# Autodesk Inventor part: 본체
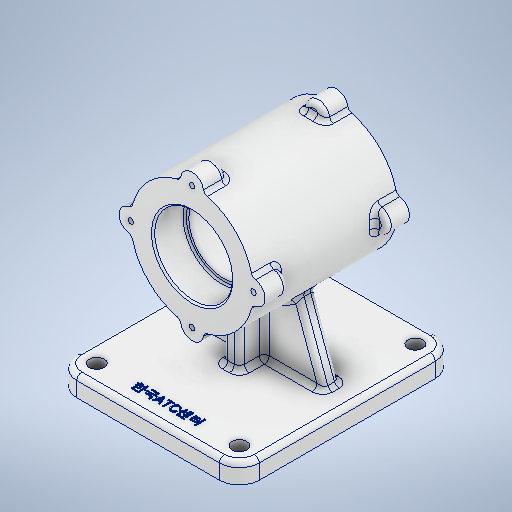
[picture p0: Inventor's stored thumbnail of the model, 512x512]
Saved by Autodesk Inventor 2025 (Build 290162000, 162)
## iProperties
Created: 2024-08
Part Number: 본체
Material: 알루미늄 6061
Document SubType Name: Modeling
Designer: SAMSUNG
Density: 2.7 g/cm^3
Appearance: 알루미늄 - 평지
Mass: 1215.33 g
Surface Area: 797.05 cm^2
Volume: 450.122 cm^3
Author: SAMSUNG
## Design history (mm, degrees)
sketch "스케치1"
  geometry: L1 (55, 70)-(-55, 70); L2 (-55, 70)-(-55, -60); L3 (-55, -60)-(55, -60); L4 (55, -60)-(55, 70); L5 (55, 70)-(-55, -60); L6 (-55, 70)-(55, -60); L7 (0, 0)-(0, 5)
  constraints: 14 end point, 2 parallel, 1 horizontal, 1 midpoint, 1 perpendicular, 1 vertical
  dimensions: "d0" = 110 distance of L2.end L3.end; "d1" = 130 distance of L1.end L2.end; "d67" = 5 distance of L7.end L7.start
extrude "돌출1" new body sketch "스케치1" distance "d2" = 12; taper "d3" = 0 deg
sketch "스케치2"
  geometry: L1 (-55, 0)-(55, 0) reference; C1 r 37 at (0, 82); 4 further points
  constraints: 3 midpoint, 1 centre point, 1 vertical alignment
  dimensions: "d5" = 37 radius of C1; "d6" = 82 distance of C1.centre point (0, 0)
extrude "돌출2" join sketch "스케치2" stored distance "d7" = 87; taper "d8" = 0 deg
sketch "스케치3"
  geometry: L1 (103, 24.5)-(82, 24.5); L2 (82, 24.5)-(82, 0); L3 (82, 0)-(103, 0); L4 (103, 0)-(103, 24.5); L5 (105.5, 43.5)-(82, 43.5); L6 (82, 43.5)-(82, 24.5); L7 (82, 24.5)-(105.5, 24.5); L8 (105.5, 24.5)-(105.5, 43.5); L9 (124.874, 0)-(25.376, 0); L10 (45, -43.5)-(119, -43.5) reference; L11 (82, -43.5)-(82, 78.341); L12 (119, 43.5)-(45, 43.5) reference; L13 (103, 0)-(103, -24.5); L14 (82, -24.5)-(82, 0); L15 (82, -24.5)-(105.5, -24.5); L16 (103, -24.5)-(82, -24.5); L17 (82, -43.5)-(82, -24.5); L18 (105.5, -43.5)-(82, -43.5); L19 (105.5, -24.5)-(105.5, -43.5); 6 further points
  constraints: 34 end point, 7 point on line, 5 symmetric about line, 4 parallel, 3 horizontal, 2 perpendicular, 1 midpoint, 1 vertical
  dimensions: "d9" = 19 distance of L7.end L5.start; "d10" = 24.5 distance of L3.end L1.start (derived); "d11" = 23.5 distance of L5.start L5.end; "d12" = 21 distance of L1.start L1.end
sketch "스케치4"
  geometry: L1 (-5, 20)-(5, 20); L2 (5, 20)-(5, -20); L3 (5, -20)-(-5, -20); L4 (-5, -20)-(-5, 20); L5 (-5, 20)-(5, -20); L6 (5, 20)-(-5, -20); L7 (-55, -70)-(55, -70) reference; 5 further points
  constraints: 12 end point, 4 midpoint, 2 parallel, 1 coincident, 1 horizontal, 1 perpendicular
  dimensions: "d20" = 10 distance of L1.start L1.end; "d22" = 40 distance of L1.end L2.end; "d69" = 50 distance between parallel lines of L7 L3
extrude "돌출3" join sketch "스케치4" stored distance "d23" = 87; taper "d24" = 0 deg
sketch "스케치5"
  geometry: L1 (25.336, 55.036)-(41, 12); L2 (5, 12)-(5, 45.339) reference; L3 (55, 12)-(-55, 12) reference; C1 r 37 at (0, 82) reference; A1 r 37 centre (0, 82) between (5, 45.339) and (25.336, 55.036) reference; 1 further point
  constraints: 2 end point, 1 point on circle, 1 point on line
  dimensions: "d25" = 14 distance of L1.end L3.start; "d26" = 110 deg angle of L1 L3
feature "리브1" sketch "스케치5" dims "d27" = 1, "d28" = 10, "d29" = 0, "d30" = 0, "d31" = 1, "d32" = 1
revolve "회전2" stored, may be unused: angle "d33" = 90 deg
sketch "스케치6"
  geometry: C1 r 7 at (0, 37); 2 further points
  constraints: 1 centre point, 1 vertical alignment, 1 other
  dimensions: "d35" = 7 radius of C1
extrude "돌출4" join sketch "스케치6" distance "d36" = 14; taper "d37" = 0 deg
sketch "스케치7"
  geometry: A1 r 7 centre (0, 119) between (6.969, 118.338) and (-6.969, 118.338) reference; 2 further points
  constraints: 1 coincident
hole "구멍1" sketch "스케치7" at (0, 119) diameter "d41" = 3.242; stored, may be unused: countersink angle "d45" = 90 deg, drill point angle "d47" = 120 deg; dims "d42" = 8, "d43" = 4, "d44" = 2, "d46" = 10
sketch "스케치8"
  geometry: L1 (-43, 48)-(43, 48); L2 (43, 48)-(43, -58); L3 (43, -58)-(-43, -58); L4 (-43, -58)-(-43, 48); L5 (-43, 48)-(43, -58); L6 (43, 48)-(-43, -58); L7 (-55, -70)-(55, -70) reference; 1 further point
  constraints: 12 end point, 2 midpoint, 2 parallel, 1 horizontal, 1 perpendicular
  dimensions: "d51" = 86 distance of L1.start L1.end; "d52" = 106 distance of L1.end L2.end; "d75" = 12 distance from line of L2.end L7
hole "구멍2" sketch "스케치8" at (-43, -58), (43, -58), (43, 48), (-43, 48) diameter "d53" = 9; stored, may be unused: countersink angle "d57" = 90 deg, drill point angle "d59" = 0 deg; dims "d54" = 8, "d55" = 4, "d56" = 2, "d58" = 10
sketch "스케치9"
  geometry: L1 (-55, -70)-(55, -70) reference; L2 (77, 0)-(-77, 0) reference; 3 further points
  constraints: 1 midpoint, 1 vertical alignment, 1 other
  dimensions: "d60" = 12 distance from line of L1 point (0, -58); "d68" = 58 distance from line of point (0, -58) L2 (derived)
feature "엠보싱1" sketch "스케치9" dims "d0" = 110, "d1" = 130, "d9" = 19, "d10" = 24.5 (derived), "d11" = 23.5, "d12" = 21, "d61" = 0.5, "d62" = 0, "d67" = 5
fillet "모깎기1" dims "d63" = 12
sketch "스케치12"
  geometry: 1 further point
fillet "모깎기2" dims "d70" = 3
fillet "모깎기3" dims "d71" = 3
fillet "모깎기4" dims "d72" = 3
fillet "모깎기5" dims "d73" = 3
fillet "모깎기6" dims "d74" = 3
fillet "모깎기7" dims "d80" = 1
chamfer "모따기3" distance "d81" = 1; stored, may be unused: second distance "d82" = 2, angle "d83" = 45 deg
chamfer "모따기4" distance "d84" = 1; stored, may be unused: second distance "d85" = 2, angle "d86" = 45 deg
sketch "스케치13"
  geometry: 1 further point
feature "΀耀΂耀΄耀Ά耀Έ耀Ί耀Ό耀Ύ耀" dims "d0" = 110, "d1" = 130, "d2" = 12, "d3" = 0, "d5" = 37, "d6" = 82, "d7" = 87, "d8" = 0, "d9" = 19, "d10" = 24.5 (derived), "d11" = 23.5, "d12" = 21, "d20" = 10, "d22" = 40, "d23" = 87, "d24" = 0, "d25" = 14, "d26" = 110 deg, "d27" = 1, "d28" = 10, "d29" = 0, "d30" = 0, "d31" = 1, "d32" = 1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
node "솔리드1"
mirror "미러1"
pattern_circular "원형 패턴1" dims angle "d39" = 360 deg
mirror "미러2"
pattern_circular "원형 패턴2" dims angle "d49" = 360 deg
mirror "미러3"
node "투영된 루프1"
feature "A9D066F2-1C7D-4E18-AEED-F7BC21143FA4" dims "d53" = 9, "d54" = 8, "d55" = 4, "d56" = 2, "d57" = 90 deg, "d58" = 10, "d59" = 0
